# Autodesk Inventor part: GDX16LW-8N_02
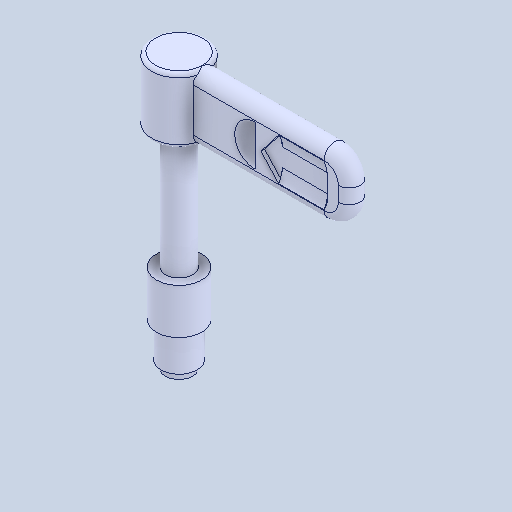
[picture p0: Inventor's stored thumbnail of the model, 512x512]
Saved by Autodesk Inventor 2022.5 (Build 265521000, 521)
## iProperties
Created: 2024-06
Part Number: GDX16LW-8N_02
Material: 一般
Document SubType Name: Modeling
Designer: ImaoCorp
Density: 1 g/cm^3
Appearance: 既定
Author: ImaoCorp
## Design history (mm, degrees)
feature "GDX16LW-8N_02"
node "ソリッド1"
